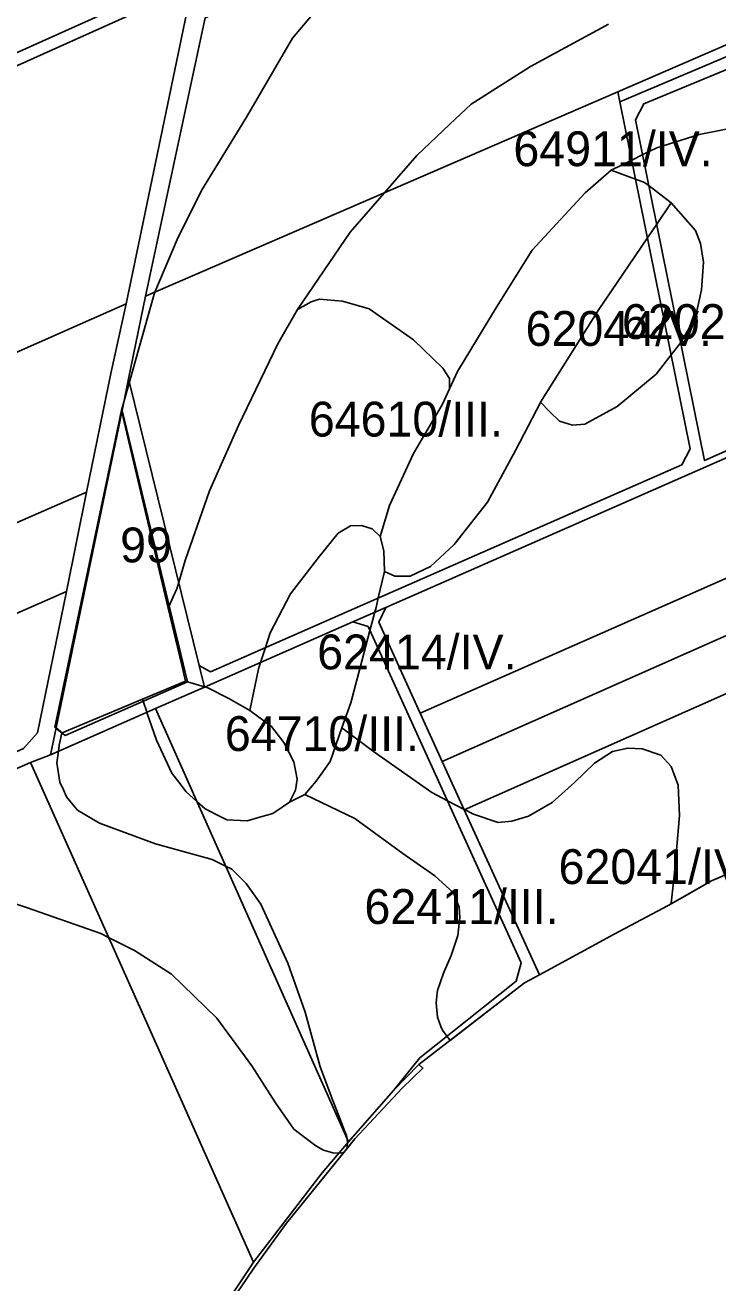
# Model space of a CAD drawing. Extents: x -522079 to -518792, y -1142400 to -1139961.
# Drawn here: x -520891 to -520592, y -1142050 to -1141508 of the extents above; entities that cross this region are included whole.
import ezdxf

# ---------------------------------------------------------------- set-up
doc = ezdxf.new("R2010")
doc.units = 0
for name, color, linetype in [('Hranice parcel', 7, 'Continuous'), ('Parcelní čísla', 7, 'Continuous'), ('Značky bodu BP', 7, 'Continuous'), ('Značky budov', 7, 'Continuous')]:
    doc.layers.add(name, color=color, linetype=linetype)

msp = doc.modelspace()

# ---------------------------------------------------------------- linework, layer by layer
at = {"layer": 'Hranice parcel'}
for points in [[(-520891.63, -1141819.53), (-520885.53, -1141812.75), (-520873.01, -1141751.95), (-520864.49, -1141709.14), (-520854, -1141657.98), (-520847.36, -1141628.04), (-520819.82, -1141495.44)], [(-520813.35, -1141504.9), (-520838.97, -1141624.77), (-520846.32, -1141660.34), (-520849.15, -1141674.02), (-520877.47, -1141810.66), (-520879.93, -1141822.22), (-520888.63, -1141825.55), (-520995.39, -1141872.52)]]:
    msp.add_lwpolyline(points, dxfattribs=at)
msp.add_lwpolyline([(-520879.93, -1141822.22), (-520877.47, -1141810.66), (-520873.57, -1141813.91), (-520820.88, -1141790.77), (-520849.15, -1141674.02), (-520846.32, -1141660.34), (-520815.91, -1141783.74), (-520813.61, -1141793.09), (-520834.71, -1141802.36)], close=True, dxfattribs=at)
at = {"layer": 'Parcelní čísla'}
for points in [[(-520659.49, -1141438.15), (-520585.72, -1141406.64), (-520580.93, -1141457.51), (-520574.39, -1141497.17), (-520572, -1141509.22), (-520635.55, -1141536.73), (-520726.9, -1141576.27), (-520838.97, -1141624.77), (-520813.35, -1141504.9)], [(-520821.3, -1141482.16), (-520824.28, -1141488.21), (-520974.97, -1141555.99), (-521072.78, -1141598.79), (-521078.78, -1141596.05), (-521084.21, -1141576.91), (-520955.18, -1141519.6), (-520826.14, -1141462.3)], [(-520819.82, -1141495.44), (-520822.47, -1141493.04), (-520972.97, -1141560.63), (-521070.28, -1141603.2), (-521076.03, -1141605.72), (-521077.42, -1141600.82), (-521072.78, -1141598.79), (-520974.97, -1141555.99), (-520824.28, -1141488.21), (-520821.3, -1141482.16)], [(-520822.47, -1141493.04), (-520819.82, -1141495.44), (-520847.36, -1141628.04), (-520954.68, -1141675.43), (-521044.98, -1141715.3), (-521058.67, -1141667), (-521074.66, -1141610.52), (-521070.28, -1141603.2), (-520972.97, -1141560.63)], [(-520572, -1141509.22), (-520571.03, -1141514.08), (-520634.69, -1141540.99), (-520635.55, -1141536.73)], [(-520624.36, -1141541.82), (-520627.91, -1141548.79), (-520598.21, -1141695.54), (-520529.1, -1141664.77), (-520528.04, -1141667.68), (-520597.66, -1141698.25), (-520735.52, -1141758.79), (-520749.7, -1141765.02), (-520813.61, -1141793.09), (-520815.91, -1141783.74), (-520811.05, -1141786.45), (-520751.28, -1141760.21), (-520608.03, -1141697.31), (-520604.47, -1141690.49), (-520634.69, -1141540.99), (-520571.03, -1141514.08), (-520569.98, -1141519.36)], [(-520627.91, -1141548.79), (-520624.36, -1141541.82), (-520569.98, -1141519.36), (-520566.58, -1141536.47), (-520557.06, -1141576.08), (-520545.85, -1141614.67), (-520536.49, -1141644.52), (-520529.1, -1141664.77), (-520598.21, -1141695.54)], [(-520608.03, -1141697.31), (-520751.28, -1141760.21), (-520811.05, -1141786.45), (-520815.91, -1141783.74), (-520846.32, -1141660.34), (-520838.97, -1141624.77), (-520726.9, -1141576.27), (-520635.55, -1141536.73), (-520634.69, -1141540.99), (-520604.47, -1141690.49)], [(-521044.98, -1141715.3), (-520954.68, -1141675.43), (-520847.36, -1141628.04), (-520854, -1141657.98), (-520864.49, -1141709.14), (-521026.62, -1141780.12)], [(-520738.58, -1141765.16), (-520735.52, -1141758.79), (-520597.66, -1141698.25), (-520528.04, -1141667.68), (-520522.71, -1141682.28), (-520510.4, -1141711.55), (-520625.27, -1141762.24), (-520720.69, -1141804.35)], [(-521026.62, -1141780.12), (-520864.49, -1141709.14), (-520873.01, -1141751.95), (-521016.76, -1141814.92)], [(-520501.37, -1141732.13), (-520539.21, -1141748.91), (-520711.18, -1141825.18), (-520720.69, -1141804.35), (-520625.27, -1141762.24), (-520510.4, -1141711.55), (-520506.95, -1141719.75)], [(-520711.18, -1141825.18), (-520539.21, -1141748.91), (-520501.37, -1141732.13), (-520491.98, -1141752.99), (-520530.72, -1141770.15), (-520701.74, -1141845.88)], [(-520873.01, -1141751.95), (-520885.53, -1141812.75), (-520891.63, -1141819.53), (-520930.02, -1141836.55), (-520997.06, -1141866.15), (-521003.04, -1141863.38), (-521016.76, -1141814.92)], [(-520701.74, -1141845.88), (-520530.72, -1141770.15), (-520491.98, -1141752.99), (-520490.19, -1141756.96), (-520458.87, -1141815.72), (-520465.55, -1141819.35), (-520477.66, -1141826.82), (-520503.7, -1141838.29), (-520515.18, -1141841.56), (-520545.58, -1141853.73), (-520565.76, -1141863.93), (-520595.23, -1141876.48), (-520613.84, -1141887.11), (-520637.23, -1141899.54), (-520669.31, -1141916.94)], [(-520720.87, -1141952.69), (-520679.41, -1141919.74), (-520677.16, -1141911.77), (-520743.17, -1141766.98), (-520749.7, -1141765.02), (-520735.52, -1141758.79), (-520738.58, -1141765.16), (-520720.69, -1141804.35), (-520711.18, -1141825.18), (-520701.74, -1141845.88), (-520669.31, -1141916.94), (-520675.72, -1141920.42), (-520721.33, -1141955.66), (-520732.26, -1141966.77)], [(-520788.5, -1141906.13), (-520834.71, -1141802.36), (-520813.61, -1141793.09), (-520749.7, -1141765.02), (-520743.17, -1141766.98), (-520677.16, -1141911.77), (-520679.41, -1141919.74), (-520720.87, -1141952.69), (-520732.26, -1141966.77), (-520751.6, -1141988.95)], [(-520837.29, -1141940.33), (-520888.63, -1141825.55), (-520879.93, -1141822.22), (-520834.71, -1141802.36), (-520788.5, -1141906.13), (-520751.6, -1141988.95), (-520762.92, -1142002.26), (-520792.44, -1142040.74)], [(-520997.93, -1141879.1), (-520995.39, -1141872.52), (-520888.63, -1141825.55), (-520837.29, -1141940.33), (-520792.44, -1142040.74), (-520794.02, -1142043.2), (-520832.63, -1142100.89), (-520865.14, -1142158.06), (-520874.16, -1142159.29), (-520905.36, -1142088.65), (-520939.85, -1142010.61), (-520967.25, -1141948.55)], [(-520865.14, -1142158.06), (-520832.63, -1142100.89), (-520794.02, -1142043.2), (-520792.44, -1142040.74), (-520762.92, -1142002.26), (-520751.6, -1141988.95), (-520732.26, -1141966.77), (-520721.33, -1141955.66), (-520719.53, -1141957.2), (-520728.5, -1141965.87), (-520748.85, -1141987.64), (-520778.35, -1142023.99), (-520792.36, -1142043.35), (-520798.04, -1142051.82), (-520812.28, -1142071.49), (-520845.48, -1142126.69), (-520864.2, -1142161.29), (-520868.95, -1142171.08), (-520870.13, -1142168.42)]]:
    msp.add_lwpolyline(points, close=True, dxfattribs=at)
at = {"layer": 'Značky bodu BP'}
for points in [[(-520750.59, -1141483.71), (-520775.72, -1141513.61), (-520795.59, -1141547.61), (-520814.88, -1141579.27), (-520825.4, -1141600.38), (-520835, -1141623.05), (-520835.33, -1141623.83), (-520845.99, -1141661.68), (-520848.28, -1141669.83), (-520848.56, -1141670.81), (-520849.41, -1141673.83), (-520855.9, -1141704.65), (-520878.15, -1141810.37), (-520877.51, -1141810.87), (-520875.07, -1141812.78), (-520876.18, -1141818.14), (-520876.52, -1141820.72), (-520877.18, -1141825.76), (-520875.88, -1141834.07), (-520874.41, -1141837.31), (-520873.04, -1141840.31), (-520870.45, -1141843.48), (-520868.37, -1141846.02), (-520858.79, -1141851.74), (-520834.71, -1141860.57), (-520810.38, -1141867.32), (-520804.51, -1141870.17), (-520801.83, -1141871.48), (-520795.62, -1141877.71), (-520789.4, -1141886.54), (-520777.75, -1141912), (-520770.24, -1141933.03), (-520763.77, -1141956.67), (-520758.33, -1141971.09), (-520755.76, -1141977.73), (-520753.41, -1141983.82), (-520752.49, -1141986.23), (-520752.2, -1141987.59), (-520752.11, -1141988.02), (-520752.02, -1141988.48), (-520752.06, -1141989.49), (-520752.11, -1141990.67), (-520752.18, -1141991.09), (-520752.32, -1141991.91), (-520748.85, -1141987.64), (-520753.57, -1141993.46), (-520753.61, -1141993.46), (-520754.4, -1141993.68), (-520755.69, -1141993.75), (-520756.06, -1141993.77), (-520758.4, -1141993.63), (-520762.35, -1141992.53), (-520765.71, -1141990.7), (-520775.16, -1141983.42), (-520783.02, -1141972.09), (-520793.28, -1141956.23), (-520808.24, -1141935.65), (-520827.9, -1141916.78), (-520843.72, -1141906.49), (-520854.94, -1141900.86), (-520858.25, -1141899.2), (-520890.31, -1141888.05), (-520908.69, -1141882.05)], [(-520639.54, -1141507.59), (-520673.15, -1141525.85), (-520698.71, -1141542.01), (-520707.92, -1141550.71), (-520722.16, -1141564.14), (-520729.88, -1141573.01), (-520736.22, -1141580.3), (-520750.87, -1141597.15), (-520773.5, -1141630.48), (-520782.08, -1141645.2), (-520798.97, -1141680.49), (-520805.8, -1141695.86), (-520811.44, -1141708.54), (-520821.96, -1141738.55), (-520824.73, -1141747.95), (-520825.56, -1141750.77), (-520827.11, -1141754.27), (-520828.8, -1141758.07), (-520829.23, -1141759.04), (-520846.04, -1141688.06), (-520849.25, -1141674.51), (-520849.41, -1141673.83), (-520848.56, -1141670.81), (-520848.28, -1141669.83), (-520845.99, -1141661.68), (-520835.33, -1141623.83), (-520835, -1141623.05), (-520825.4, -1141600.38), (-520814.88, -1141579.27), (-520795.59, -1141547.61), (-520775.72, -1141513.61), (-520750.59, -1141483.71)], [(-520580.87, -1141551.24), (-520600.51, -1141555.1), (-520618.75, -1141560.77), (-520624.88, -1141563.78), (-520629.61, -1141566.1), (-520638.49, -1141570.46), (-520649.69, -1141580.29), (-520672.45, -1141604.88), (-520687.85, -1141629.46), (-520704.66, -1141657.21), (-520708.14, -1141664.65), (-520708.14, -1141660.2), (-520710.91, -1141655.76), (-520723.65, -1141643.53), (-520742.76, -1141630.2), (-520754.11, -1141626.86), (-520764.08, -1141626.03), (-520765.88, -1141626.59), (-520767.68, -1141627.15), (-520773.5, -1141630.48), (-520750.87, -1141597.15), (-520736.22, -1141580.3), (-520729.88, -1141573.01), (-520722.16, -1141564.14), (-520707.92, -1141550.71), (-520698.71, -1141542.01), (-520673.15, -1141525.85), (-520639.54, -1141507.59)], [(-520575.63, -1141868.13), (-520595.23, -1141876.48), (-520604.76, -1141881.92), (-520604.78, -1141881.93), (-520612.62, -1141886.41), (-520612.59, -1141886.11), (-520611.53, -1141875.85), (-520610.93, -1141870.12), (-520609.06, -1141848.41), (-520609.6, -1141835.27), (-520612.54, -1141827.23), (-520617.08, -1141822.4), (-520625.1, -1141819.72), (-520631.25, -1141819.45), (-520637.93, -1141820.79), (-520645.68, -1141825.88), (-520654.23, -1141834.19), (-520663.85, -1141842.77), (-520674, -1141848.67), (-520681.22, -1141850.82), (-520687.1, -1141851.35), (-520697.79, -1141847.87), (-520701.65, -1141845.84), (-520701.79, -1141845.77), (-520708.96, -1141842.01), (-520715.69, -1141838.49), (-520740.81, -1141820.79), (-520754.42, -1141810.57), (-520750.56, -1141799.92), (-520745.01, -1141778.63), (-520742.37, -1141768.74), (-520740.27, -1141760.87), (-520739.71, -1141758.79), (-520738.75, -1141754.71), (-520736.09, -1141743.3), (-520731.62, -1141745.36), (-520724.96, -1141745.36), (-520716.21, -1141741.15), (-520706.06, -1141731.67), (-520691.7, -1141713.41), (-520679.45, -1141690.93), (-520668.95, -1141670.56), (-520668.84, -1141670.38), (-520664.91, -1141674.55), (-520660.67, -1141678.59), (-520655.16, -1141680.29), (-520649.86, -1141679.87), (-520635.86, -1141672.21), (-520619.1, -1141658.38), (-520612.65, -1141650.01), (-520608.51, -1141644.63), (-520608.29, -1141644.34), (-520602.14, -1141633.7), (-520599.59, -1141622), (-520598.74, -1141610.09), (-520600.02, -1141602), (-520602.14, -1141596.47), (-520612.58, -1141584.51), (-520622.15, -1141577.23), (-520624.13, -1141575.73), (-520627.95, -1141574.33), (-520638.49, -1141570.46), (-520629.61, -1141566.1), (-520624.88, -1141563.78), (-520618.75, -1141560.77), (-520600.51, -1141555.1), (-520580.87, -1141551.24)], [(-520908.69, -1141882.05), (-520890.31, -1141888.05), (-520858.25, -1141899.2), (-520854.94, -1141900.86), (-520843.72, -1141906.49), (-520827.9, -1141916.78), (-520808.24, -1141935.65), (-520793.28, -1141956.23), (-520783.02, -1141972.09), (-520775.16, -1141983.42), (-520765.71, -1141990.7), (-520762.35, -1141992.53), (-520758.4, -1141993.63), (-520756.06, -1141993.77), (-520755.69, -1141993.75), (-520754.4, -1141993.68), (-520753.61, -1141993.46), (-520753.57, -1141993.46), (-520778.35, -1142023.99), (-520792.36, -1142043.35), (-520798.04, -1142051.82)]]:
    msp.add_lwpolyline(points, dxfattribs=at)
for points in [[(-520612.58, -1141584.51), (-520618.82, -1141593.72), (-520622.83, -1141599.65), (-520643.74, -1141630.52), (-520668.84, -1141670.38), (-520668.95, -1141670.56), (-520679.45, -1141690.93), (-520691.7, -1141713.41), (-520706.06, -1141731.67), (-520716.21, -1141741.15), (-520724.96, -1141745.36), (-520731.62, -1141745.36), (-520736.09, -1141743.3), (-520736.33, -1141734.35), (-520738.02, -1141728.3), (-520733.89, -1141714.93), (-520723.65, -1141692.43), (-520716.42, -1141680.35), (-520711.18, -1141671.59), (-520708.14, -1141664.65), (-520704.66, -1141657.21), (-520687.85, -1141629.46), (-520672.45, -1141604.88), (-520649.69, -1141580.29), (-520638.49, -1141570.46), (-520627.95, -1141574.33), (-520624.13, -1141575.73), (-520622.15, -1141577.23)], [(-520649.86, -1141679.87), (-520655.16, -1141680.29), (-520660.67, -1141678.59), (-520664.91, -1141674.55), (-520668.84, -1141670.38), (-520643.74, -1141630.52), (-520622.83, -1141599.65), (-520618.82, -1141593.72), (-520612.58, -1141584.51), (-520602.14, -1141596.47), (-520600.02, -1141602), (-520598.74, -1141610.09), (-520599.59, -1141622), (-520602.14, -1141633.7), (-520608.29, -1141644.34), (-520608.51, -1141644.63), (-520612.65, -1141650.01), (-520619.1, -1141658.38), (-520635.86, -1141672.21)], [(-520708.14, -1141664.65), (-520711.18, -1141671.59), (-520716.42, -1141680.35), (-520723.65, -1141692.43), (-520733.89, -1141714.93), (-520738.02, -1141728.3), (-520741.4, -1141724.91), (-520745.98, -1141723.46), (-520750.8, -1141723.7), (-520756.11, -1141726.85), (-520764.55, -1141737.25), (-520776.61, -1141752.98), (-520785.3, -1141769.68), (-520787.39, -1141776.06), (-520789.49, -1141782.5), (-520790.36, -1141785.16), (-520794.08, -1141803.21), (-520803.15, -1141797.96), (-520812.23, -1141793.34), (-520813.41, -1141793), (-520813.65, -1141792.93), (-520820.97, -1141790.81), (-520821.76, -1141790.58), (-520823.4, -1141783.67), (-520829.23, -1141759.04), (-520828.8, -1141758.07), (-520827.11, -1141754.27), (-520825.56, -1141750.77), (-520824.73, -1141747.95), (-520821.96, -1141738.55), (-520811.44, -1141708.54), (-520805.8, -1141695.86), (-520798.97, -1141680.49), (-520782.08, -1141645.2), (-520773.5, -1141630.48), (-520767.68, -1141627.15), (-520765.88, -1141626.59), (-520764.08, -1141626.03), (-520754.11, -1141626.86), (-520742.76, -1141630.2), (-520723.65, -1141643.53), (-520710.91, -1141655.76), (-520708.14, -1141660.2)], [(-520874.97, -1141812.74), (-520875.07, -1141812.78), (-520877.51, -1141810.87), (-520878.15, -1141810.37), (-520855.9, -1141704.65), (-520849.41, -1141673.83), (-520849.25, -1141674.51), (-520846.04, -1141688.06), (-520829.23, -1141759.04), (-520823.4, -1141783.67), (-520821.76, -1141790.58), (-520840.33, -1141798.31), (-520842.08, -1141799.04)], [(-520770.34, -1141839.36), (-520776.96, -1141842.69), (-520774.4, -1141837.44), (-520773.64, -1141832.7), (-520775.17, -1141825.26), (-520779.51, -1141816.93), (-520784.75, -1141810.01), (-520794.08, -1141803.21), (-520790.36, -1141785.16), (-520789.49, -1141782.5), (-520787.39, -1141776.06), (-520785.3, -1141769.68), (-520776.61, -1141752.98), (-520764.55, -1141737.25), (-520756.11, -1141726.85), (-520750.8, -1141723.7), (-520745.98, -1141723.46), (-520741.4, -1141724.91), (-520738.02, -1141728.3), (-520736.33, -1141734.35), (-520736.09, -1141743.3), (-520738.75, -1141754.71), (-520739.71, -1141758.79), (-520740.27, -1141760.87), (-520742.37, -1141768.74), (-520745.01, -1141778.63), (-520750.56, -1141799.92), (-520754.42, -1141810.57), (-520759.49, -1141825.09), (-520765.52, -1141833.56)], [(-520794.08, -1141803.21), (-520784.75, -1141810.01), (-520779.51, -1141816.93), (-520775.17, -1141825.26), (-520773.64, -1141832.7), (-520774.4, -1141837.44), (-520776.96, -1141842.69), (-520780.19, -1141844.86), (-520784.24, -1141847.57), (-520789.34, -1141848.99), (-520795.23, -1141850.64), (-520804.05, -1141850.26), (-520806.58, -1141848.97), (-520813.38, -1141845.51), (-520816.89, -1141842.38), (-520821.56, -1141838.21), (-520824.7, -1141834.06), (-520827.69, -1141830.13), (-520834.33, -1141815.91), (-520838.4, -1141803.98), (-520838.5, -1141803.7), (-520840.04, -1141799.18), (-520840.17, -1141798.78), (-520840.33, -1141798.31), (-520821.76, -1141790.58), (-520820.97, -1141790.81), (-520813.65, -1141792.93), (-520813.41, -1141793), (-520812.23, -1141793.34), (-520803.15, -1141797.96)], [(-520707.86, -1141945.25), (-520675.72, -1141920.42), (-520721.33, -1141955.66), (-520719.53, -1141957.2), (-520728.5, -1141965.87), (-520748.85, -1141987.64), (-520752.32, -1141991.91), (-520752.18, -1141991.09), (-520752.11, -1141990.67), (-520752.06, -1141989.49), (-520752.02, -1141988.48), (-520752.11, -1141988.02), (-520752.2, -1141987.59), (-520752.49, -1141986.23), (-520753.41, -1141983.82), (-520755.76, -1141977.73), (-520758.33, -1141971.09), (-520763.77, -1141956.67), (-520770.24, -1141933.03), (-520777.75, -1141912), (-520789.4, -1141886.54), (-520795.62, -1141877.71), (-520801.83, -1141871.48), (-520804.51, -1141870.17), (-520810.38, -1141867.32), (-520834.71, -1141860.57), (-520858.79, -1141851.74), (-520868.37, -1141846.02), (-520870.45, -1141843.48), (-520873.04, -1141840.31), (-520874.41, -1141837.31), (-520875.88, -1141834.07), (-520877.18, -1141825.76), (-520876.52, -1141820.72), (-520876.18, -1141818.14), (-520875.07, -1141812.78), (-520874.97, -1141812.74), (-520842.08, -1141799.04), (-520840.33, -1141798.31), (-520840.17, -1141798.78), (-520840.04, -1141799.18), (-520838.5, -1141803.7), (-520838.4, -1141803.98), (-520834.33, -1141815.91), (-520827.69, -1141830.13), (-520824.7, -1141834.06), (-520821.56, -1141838.21), (-520816.89, -1141842.38), (-520813.38, -1141845.51), (-520806.58, -1141848.97), (-520804.05, -1141850.26), (-520795.23, -1141850.64), (-520789.34, -1141848.99), (-520784.24, -1141847.57), (-520780.19, -1141844.86), (-520776.96, -1141842.69), (-520770.34, -1141839.36), (-520748.83, -1141849.75), (-520728.25, -1141864.76), (-520714.36, -1141874.41), (-520706.34, -1141881.65), (-520703.93, -1141887.81), (-520703.67, -1141892.37), (-520704.47, -1141900.14), (-520707.41, -1141908.72), (-520710.62, -1141916.23), (-520713.29, -1141923.74), (-520713.39, -1141924.73), (-520713.82, -1141929.1), (-520713.29, -1141935.26), (-520711.78, -1141939.24), (-520711.15, -1141940.89), (-520709.23, -1141943.44), (-520708.14, -1141944.88)], [(-520613.84, -1141887.11), (-520637.23, -1141899.54), (-520669.31, -1141916.94), (-520675.72, -1141920.42), (-520707.86, -1141945.25), (-520708.14, -1141944.88), (-520709.23, -1141943.44), (-520711.15, -1141940.89), (-520711.78, -1141939.24), (-520713.29, -1141935.26), (-520713.82, -1141929.1), (-520713.39, -1141924.73), (-520713.29, -1141923.74), (-520710.62, -1141916.23), (-520707.41, -1141908.72), (-520704.47, -1141900.14), (-520703.67, -1141892.37), (-520703.93, -1141887.81), (-520706.34, -1141881.65), (-520714.36, -1141874.41), (-520728.25, -1141864.76), (-520748.83, -1141849.75), (-520770.34, -1141839.36), (-520765.52, -1141833.56), (-520759.49, -1141825.09), (-520754.42, -1141810.57), (-520740.81, -1141820.79), (-520715.69, -1141838.49), (-520708.96, -1141842.01), (-520701.79, -1141845.77), (-520701.65, -1141845.84), (-520697.79, -1141847.87), (-520687.1, -1141851.35), (-520681.22, -1141850.82), (-520674, -1141848.67), (-520663.85, -1141842.77), (-520654.23, -1141834.19), (-520645.68, -1141825.88), (-520637.93, -1141820.79), (-520631.25, -1141819.45), (-520625.1, -1141819.72), (-520617.08, -1141822.4), (-520612.54, -1141827.23), (-520609.6, -1141835.27), (-520609.06, -1141848.41), (-520610.93, -1141870.12), (-520611.53, -1141875.85), (-520612.59, -1141886.11), (-520612.62, -1141886.41), (-520604.78, -1141881.93), (-520604.76, -1141881.92)]]:
    msp.add_lwpolyline(points, close=True, dxfattribs=at)
at = {"layer": 'Značky budov'}
msp.add_lwpolyline([(-520873.57, -1141813.91), (-520877.47, -1141810.66), (-520849.15, -1141674.02), (-520820.88, -1141790.77)], close=True, dxfattribs=at)

# ---------------------------------------------------------------- texts
at = {"layer": 'Značky bodu BP'}
for s, rotation, p in [('64911/IV.', 360, (-520680.57, -1141568.74)), ('62044/V.', 360, (-520675.3, -1141646.15)), ('62024/V.', 0, (-520633.79, -1141643.17)), ('64610/III.', 360, (-520768.69, -1141685.18)), ('99', 360, (-520849.95, -1141739.37)), ('62414/IV.', 360, (-520765.08, -1141785.45)), ('64710/III.', 360, (-520804.86, -1141820.61)), ('62041/IV.', 360, (-520661.11, -1141877.91)), ('62411/III.', 0, (-520744.72, -1141895.11))]:
    msp.add_text(s, height=15, rotation=rotation, dxfattribs=at).set_placement(p)

doc.saveas('drawing.dxf')
